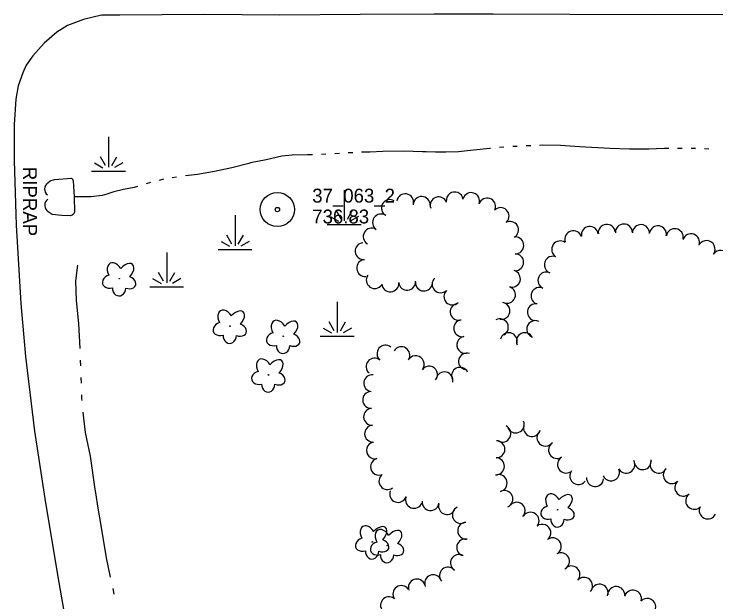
# Model space of a CAD drawing. Extents: x 589250 to 1188077, y 162953 to 363065.
# Drawn here: x 593139.8 to 593442.4, y 164801.7 to 165055.2 of the extents above; entities that cross this region are included whole.
import ezdxf

# ---------------------------------------------------------------- set-up
doc = ezdxf.new("R2010")
doc.units = 0
for name, color, linetype in [('E_DRN', 7, 'Continuous'), ('E_DRN_RipRap', 7, 'Continuous'), ('E_DRN_RipRap_Text', 7, 'Continuous'), ('E_LAND_TreeLine_P', 7, 'Continuous'), ('E_LAND_Vegetation', 7, 'Continuous'), ('E_MAP_PassPoints', 7, 'Continuous'), ('E_RDWY', 7, 'Continuous'), ('E_WTR_FlowLine', 7, 'Continuous'), ('E_WTR_Wetland', 7, 'Continuous')]:
    doc.layers.add(name, color=color, linetype=linetype)

# ---------------------------------------------------------------- blocks, each defined once
blk = doc.blocks.new('POINT_DISPLAY')
blk.add_line((0, 0), (0, 0))

msp = doc.modelspace()

# ---------------------------------------------------------------- linework, layer by layer
at = {"layer": 'E_DRN'}
for centre, radius, start, end in [((593156.19, 164979.78), 3.26, 125.1717, 231.4319), ((593156.45, 164972.77), 3.45, 128.3211, 234.5814)]:
    msp.add_arc(centre, radius, start, end, dxfattribs=at)
at = {"layer": 'E_DRN_RipRap'}
for p, q in [((593154.31, 164982.45), (593155.38, 164983.31)), ((593155.38, 164983.31), (593157.22, 164983.93)), ((593157.22, 164983.93), (593164.52, 164984.49)), ((593164.52, 164984.49), (593165.02, 164984.08)), ((593165.02, 164984.08), (593165.29, 164983.32)), ((593165.29, 164983.32), (593165.73, 164976.46)), ((593165.73, 164976.46), (593165.78, 164969.86)), ((593156.23, 164968.85), (593154.45, 164969.96)), ((593165.78, 164969.86), (593165.46, 164968.95)), ((593160.42, 164968.34), (593156.23, 164968.85)), ((593164.03, 164968.21), (593160.42, 164968.34)), ((593164.88, 164968.48), (593164.03, 164968.21)), ((593165.46, 164968.95), (593164.88, 164968.48))]:
    msp.add_line(p, q, dxfattribs=at)
at = {"layer": 'E_LAND_TreeLine_P'}
for centre, radius, start, end in [((593329.75, 164974.88), 3.64, 7.2134, 187.2134), ((593308.36, 164974.08), 3.64, 349.5475, 169.5475), ((593315.54, 164972.94), 3.64, 358.4967, 178.4967), ((593322.82, 164972.76), 3.64, 19.8862, 199.8862), ((593336.85, 164974.59), 3.64, 341.2448, 161.2448), ((593343.75, 164972.25), 3.64, 341.2448, 161.2448), ((593301.79, 164971.57), 3.64, 59.2686, 239.2686), ((593349.55, 164968.11), 3.64, 315.9963, 135.9963), ((593297.97, 164965.37), 3.64, 56.0727, 236.0727), ((593353.62, 164962.14), 3.64, 300.0679, 120.0679), ((593388.02, 164959.95), 3.68, 7.1667, 187.1667), ((593395.33, 164960.87), 3.68, 7.1667, 187.1667), ((593402.69, 164961.01), 3.68, 1.0281, 181.0281), ((593410.04, 164960.76), 3.68, 357.0874, 177.0874), ((593417.37, 164960.23), 3.68, 350.3061, 170.3061), ((593293.95, 164959.31), 3.64, 59.4309, 239.4309), ((593380.92, 164958.12), 3.68, 17.1599, 197.1599), ((593424.63, 164959), 3.68, 350.3061, 170.3061), ((593431.63, 164956.79), 3.68, 340.3602, 160.3602), ((593355.89, 164955.47), 3.64, 269.6417, 89.6417), ((593375.25, 164953.71), 3.68, 55.357, 235.357), ((593438.32, 164953.86), 3.68, 325.0659, 145.0659), ((593290.47, 164952.99), 3.64, 95.233, 275.233), ((593355.84, 164948.19), 3.64, 269.6417, 89.6417), ((593444.36, 164949.64), 3.68, 325.0659, 145.0659), ((593291.13, 164945.73), 3.64, 95.233, 275.233), ((593372.07, 164947.13), 3.68, 69.574, 249.574), ((593295.29, 164940.53), 3.64, 145.5372, 325.5372), ((593354.42, 164941.11), 3.64, 253.6584, 73.6584), ((593369.29, 164940.36), 3.64, 65.6946, 245.6946), ((593301.99, 164939.07), 3.64, 185.3245, 5.3245), ((593309.24, 164939.75), 3.64, 185.3245, 5.3245), ((593316.5, 164939.45), 3.64, 175.6585, 355.6585), ((593323.66, 164938.69), 3.64, 134.1091, 314.1091), ((593352.3, 164934.15), 3.64, 249.6763, 69.6763), ((593366.29, 164933.72), 3.64, 65.6946, 245.6946), ((593328.73, 164933.46), 3.64, 134.1091, 314.1091), ((593331.45, 164926.85), 3.64, 106.7367, 286.7367), ((593349.94, 164927.27), 3.64, 261.5592, 81.5592), ((593364.74, 164926.67), 3.64, 81.7612, 261.7612), ((593333.01, 164919.75), 3.64, 101.387, 281.387), ((593349.25, 164920.14), 3.64, 298.6014, 118.6014), ((593364.47, 164919.41), 3.64, 64.366, 244.366), ((593334.31, 164912.58), 3.64, 99.4623, 279.4623), ((593353.07, 164914.19), 3.64, 346.8399, 166.8399), ((593359.99, 164914.18), 3.64, 25.5786, 205.5786), ((593299.88, 164908.8), 3.64, 49.8325, 229.8325), ((593306.78, 164908.13), 3.64, 328.0612, 148.0612), ((593335.05, 164905.43), 3.64, 73.8428, 253.8428), ((593295.18, 164903.24), 3.64, 49.8325, 229.8325), ((593312.96, 164904.28), 3.64, 321.6912, 141.6912), ((593318.67, 164899.76), 3.64, 321.6912, 141.6912), ((593332.04, 164899.26), 3.64, 25.8734, 205.8734), ((593325.35, 164897.28), 3.64, 347.4748, 167.4748), ((593294.19, 164896.08), 3.64, 83.6957, 263.6957), ((593293.71, 164888.84), 3.64, 93.2452, 273.2452), ((593294.12, 164881.57), 3.64, 93.2452, 273.2452), ((593356.03, 164878.29), 3.68, 202.4814, 22.4814), ((593294.54, 164874.3), 3.64, 93.2452, 273.2452), ((593350.28, 164874.35), 3.68, 242.8248, 62.8248), ((593363.05, 164876.79), 3.68, 163.374, 343.374), ((593368.9, 164872.62), 3.68, 136.1872, 316.1872), ((593295.34, 164867.09), 3.64, 104.117, 284.117), ((593347.72, 164867.59), 3.68, 268.2345, 88.2345), ((593373.88, 164867.25), 3.68, 121.7546, 301.7546), ((593297.12, 164860.03), 3.64, 104.117, 284.117), ((593347.49, 164860.23), 3.68, 268.2345, 88.2345), ((593377.76, 164861), 3.68, 121.7546, 301.7546), ((593403.7, 164860.92), 3.68, 208.7555, 28.7555), ((593410.82, 164862.47), 3.68, 188.3625, 8.3625), ((593417.68, 164860.95), 3.68, 153.2365, 333.2365), ((593383.07, 164856.06), 3.68, 143.1155, 323.1155), ((593397.15, 164857.59), 3.68, 202.6582, 22.6582), ((593423.37, 164856.47), 3.68, 133.0012, 313.0012), ((593300.73, 164853.85), 3.64, 127.3492, 307.3492), ((593348.65, 164853), 3.68, 282.263, 102.263), ((593390.29, 164855.16), 3.68, 175.4687, 355.4687), ((593428.35, 164851.04), 3.68, 132.2967, 312.2967), ((593305.35, 164848.32), 3.64, 159.3779, 339.3779), ((593351.16, 164846.11), 3.68, 293.2579, 113.2579), ((593312.16, 164845.76), 3.64, 159.3779, 339.3779), ((593433.02, 164845.36), 3.68, 128.0263, 308.0263), ((593319.36, 164844.78), 3.64, 173.578, 353.578), ((593326.43, 164843.08), 3.64, 165.301, 345.301), ((593332.37, 164839.22), 3.64, 114.1949, 294.1949), ((593356.45, 164841.03), 3.68, 317.163, 137.163), ((593438.86, 164841.2), 3.68, 154.9547, 334.9547), ((593362.42, 164836.75), 3.68, 325.4363, 145.4363), ((593334.7, 164832.43), 3.64, 92.4781, 272.4781), ((593367.51, 164831.54), 3.68, 308.0551, 128.0551), ((593334.27, 164825.23), 3.64, 75.9097, 255.9097), ((593372.05, 164825.75), 3.68, 308.0551, 128.0551), ((593331.53, 164818.55), 3.64, 59.9759, 239.9759), ((593375.56, 164819.28), 3.68, 298.3049, 118.3049), ((593326.87, 164813.09), 3.64, 40.8337, 220.8337), ((593380.06, 164813.59), 3.68, 317.7585, 137.7585), ((593320.45, 164809.8), 3.64, 22.4814, 202.4814), ((593385.51, 164808.65), 3.68, 317.7585, 137.7585), ((593313.41, 164807.97), 3.64, 19.463, 199.463), ((593392.2, 164805.72), 3.68, 339.3779, 159.3779), ((593306.75, 164805.14), 3.64, 34.9275, 214.9275), ((593399.41, 164804.7), 3.68, 357.3215, 177.3215), ((593406.57, 164803.2), 3.68, 343.9383, 163.9383), ((593301.43, 164800.3), 3.64, 53.1593, 233.1593), ((593412.76, 164799.61), 3.68, 316.6645, 136.6645)]:
    msp.add_arc(centre, radius, start, end, dxfattribs=at)
at = {"layer": 'E_LAND_Vegetation'}
for centre in [(593185.13, 164941.12), (593232.83, 164920.67), (593255.84, 164916.3), (593249.45, 164899.62), (593374.14, 164841.48), (593294.2, 164827.67), (593300.66, 164826.05)]:
    msp.add_circle(centre, 0.128, dxfattribs=at)
for centre, major_axis, ratio in [((593183.2, 164944.08), (2.06, -3.68), 0.691916), ((593187.71, 164943.74), (-3.19, -3.52), 0.560249), ((593181.41, 164939.92), (3.48, 0.97), 0.782863), ((593188.8, 164939.52), (-3.4, 1.25), 0.716896), ((593185.03, 164937.14), (0.07, 3.45), 0.832022), ((593230.9, 164923.63), (2.06, -3.68), 0.691916), ((593235.41, 164923.29), (-3.19, -3.52), 0.560249), ((593229.11, 164919.47), (3.48, 0.97), 0.782863), ((593236.51, 164919.07), (-3.4, 1.25), 0.716896), ((593253.91, 164919.26), (2.06, -3.68), 0.691916), ((593258.42, 164918.92), (-3.19, -3.52), 0.560249), ((593232.74, 164916.69), (0.07, 3.45), 0.832022), ((593252.12, 164915.11), (3.48, 0.97), 0.782863), ((593259.51, 164914.7), (-3.4, 1.25), 0.716896), ((593255.75, 164912.32), (0.07, 3.45), 0.832022), ((593247.53, 164902.58), (2.06, -3.68), 0.691916), ((593252.04, 164902.24), (-3.19, -3.52), 0.560249), ((593245.73, 164898.43), (3.48, 0.97), 0.782863), ((593253.13, 164898.02), (-3.4, 1.25), 0.716896), ((593249.36, 164895.64), (0.07, 3.45), 0.832022), ((593372.21, 164844.44), (2.06, -3.68), 0.691916), ((593376.72, 164844.1), (-3.19, -3.52), 0.560249), ((593370.42, 164840.29), (3.48, 0.97), 0.782863), ((593377.81, 164839.88), (-3.4, 1.25), 0.716896), ((593374.05, 164837.5), (0.07, 3.45), 0.832022), ((593292.27, 164830.63), (2.06, -3.68), 0.691916), ((593296.78, 164830.29), (-3.19, -3.52), 0.560249), ((593298.73, 164829.01), (2.06, -3.68), 0.691916), ((593303.24, 164828.67), (-3.19, -3.52), 0.560249), ((593290.48, 164826.47), (3.48, 0.97), 0.782863), ((593296.94, 164824.86), (3.48, 0.97), 0.782863), ((593297.88, 164826.07), (-3.4, 1.25), 0.716896), ((593304.33, 164824.45), (-3.4, 1.25), 0.716896), ((593294.11, 164823.69), (0.07, 3.45), 0.832022), ((593300.57, 164822.07), (0.07, 3.45), 0.832022)]:
    msp.add_ellipse(centre, major_axis=major_axis, ratio=ratio, start_param=1.570796, end_param=4.712389, dxfattribs=at)
at = {"layer": 'E_MAP_PassPoints'}
for radius in [7.38, 0.945]:
    msp.add_circle((593253.31, 164970.94), radius, dxfattribs=at)
at = {"layer": 'E_RDWY'}
for p, q in [((593177.41, 165054.78), (593169.66, 165052.82)), ((593185.33, 165054.78), (593177.41, 165054.78)), ((593221.93, 165054.99), (593185.33, 165054.78)), ((593254.3, 165054.81), (593221.93, 165054.99)), ((593288.95, 165055.01), (593254.3, 165054.81)), ((593320.93, 165055.24), (593288.95, 165055.01)), ((593346.39, 165055.15), (593320.93, 165055.24)), ((593379.36, 165055.03), (593346.39, 165055.15)), ((593415.78, 165054.96), (593379.36, 165055.03)), ((593453.05, 165055.01), (593415.78, 165054.96)), ((593169.66, 165052.82), (593162.8, 165050.29)), ((593162.8, 165050.29), (593158.25, 165047.42)), ((593158.25, 165047.42), (593152.69, 165042.71)), ((593152.69, 165042.71), (593147.81, 165037.18)), ((593147.81, 165037.18), (593145.03, 165033.24)), ((593145.03, 165033.24), (593143.5, 165029.91)), ((593143.5, 165029.91), (593141.56, 165024.27)), ((593141.56, 165024.27), (593140.57, 165018.56)), ((593140.57, 165018.56), (593139.85, 165007.63)), ((593139.85, 165007.63), (593139.75, 164992.08)), ((593139.75, 164992.08), (593140.63, 164964.19)), ((593140.63, 164964.19), (593142.63, 164930.43)), ((593142.63, 164930.43), (593144.66, 164907.64)), ((593144.66, 164907.64), (593148.62, 164875.32)), ((593148.62, 164875.32), (593153.34, 164844.53)), ((593153.34, 164844.53), (593159.02, 164810.13)), ((593159.02, 164810.13), (593165.53, 164774.24))]:
    msp.add_line(p, q, dxfattribs=at)
at = {"layer": 'E_WTR_FlowLine'}
for p, q in [((593344.92, 164997.27), (593337.8, 164996.6)), ((593345.25, 164997.3), (593344.92, 164997.27)), ((593350.99, 164997.83), (593349.08, 164997.66)), ((593356.75, 164998.15), (593354.83, 164998.05)), ((593361.49, 164998.39), (593360.59, 164998.35)), ((593362.51, 164998.44), (593361.49, 164998.39)), ((593367.64, 164998.68), (593366.35, 164998.62)), ((593375.3, 164998.54), (593367.64, 164998.68)), ((593383.54, 164997.96), (593375.3, 164998.54)), ((593388.76, 164997.71), (593383.54, 164997.96)), ((593394.18, 164997.43), (593388.76, 164997.71)), ((593396.68, 164997.31), (593394.18, 164997.43)), ((593405.18, 164996.93), (593396.68, 164997.31)), ((593413.48, 164997.02), (593405.18, 164996.93)), ((593420.02, 164997.31), (593413.48, 164997.02)), ((593422.03, 164997.31), (593420.02, 164997.31)), ((593427.7, 164997.31), (593425.88, 164997.31)), ((593427.8, 164997.31), (593427.7, 164997.31)), ((593433.57, 164997.28), (593431.64, 164997.29)), ((593439.33, 164997.01), (593437.41, 164997.1)), ((593255.15, 164993.89), (593248.5, 164992.39)), ((593259.72, 164994.37), (593255.15, 164993.89)), ((593266.35, 164994.52), (593259.72, 164994.37)), ((593268.49, 164994.59), (593266.35, 164994.52)), ((593274.25, 164994.77), (593272.33, 164994.71)), ((593280.01, 164995.11), (593278.09, 164994.99)), ((593285.77, 164995.46), (593283.85, 164995.34)), ((593293.14, 164995.74), (593289.61, 164995.62)), ((593298.8, 164996.03), (593293.14, 164995.74)), ((593307.75, 164996.09), (593298.8, 164996.03)), ((593315.93, 164995.8), (593307.75, 164996.09)), ((593317.46, 164995.76), (593315.93, 164995.8)), ((593321.44, 164995.65), (593317.46, 164995.76)), ((593325.9, 164995.67), (593321.44, 164995.65)), ((593331.44, 164995.87), (593325.9, 164995.67)), ((593337.8, 164996.6), (593331.44, 164995.87)), ((593240.97, 164990.86), (593233.62, 164988.99)), ((593241.7, 164991.05), (593240.97, 164990.86)), ((593248.5, 164992.39), (593241.7, 164991.05)), ((593233.62, 164988.99), (593226.18, 164987.29)), ((593209.85, 164984.93), (593207.95, 164984.67)), ((593218.85, 164986.09), (593213.66, 164985.42)), ((593226.18, 164987.29), (593218.85, 164986.09)), ((593198.58, 164982.56), (593196.73, 164982.07)), ((593204.16, 164984.02), (593202.3, 164983.53)), ((593182.78, 164978.64), (593179.71, 164977.6)), ((593187, 164979.59), (593182.78, 164978.64)), ((593191.57, 164980.46), (593187, 164979.59)), ((593193.05, 164980.94), (593191.57, 164980.46)), ((593173.06, 164976.49), (593165.73, 164976.46)), ((593177.72, 164977.06), (593173.06, 164976.49)), ((593179.71, 164977.6), (593177.72, 164977.06)), ((593166.46, 164940.13), (593167.19, 164946.99)), ((593166.67, 164931.69), (593166.46, 164940.13)), ((593167.62, 164921.87), (593166.67, 164931.69)), ((593168.24, 164910.98), (593167.62, 164921.87)), ((593168.55, 164903.51), (593168.44, 164906)), ((593168.82, 164896.05), (593168.74, 164898.54)), ((593169.04, 164889.5), (593168.99, 164891.07)), ((593169.13, 164888.58), (593169.04, 164889.5)), ((593169.9, 164881), (593169.63, 164883.62)), ((593170.62, 164874.87), (593169.9, 164881)), ((593172.78, 164864.65), (593170.62, 164874.87)), ((593174.77, 164850.38), (593172.78, 164864.65)), ((593175.12, 164847.95), (593174.77, 164850.38)), ((593175.83, 164843.05), (593175.12, 164847.95)), ((593177.51, 164833.79), (593175.83, 164843.05)), ((593179.67, 164820.81), (593177.51, 164833.79)), ((593181.36, 164812.37), (593179.67, 164820.81)), ((593182.99, 164805.08), (593182.44, 164807.51))]:
    msp.add_line(p, q, dxfattribs=at)
at = {"layer": 'E_WTR_Wetland'}
for p, q in [((593180.52, 165002.36), (593180.52, 164989.16)), ((593179.17, 164989.91), (593177, 164993.7)), ((593181.93, 164989.91), (593184.09, 164993.7)), ((593174.46, 164991.05), (593178.09, 164988.99)), ((593186.64, 164991.05), (593183.01, 164989)), ((593173.22, 164987.53), (593187.78, 164987.54)), ((593282.12, 164979.26), (593282.13, 164966.06)), ((593280.77, 164966.81), (593278.6, 164970.6)), ((593283.53, 164966.82), (593285.7, 164970.61)), ((593235.04, 164968.53), (593235.05, 164955.32)), ((593276.06, 164967.95), (593279.69, 164965.9)), ((593288.24, 164967.96), (593284.62, 164965.9)), ((593274.82, 164964.43), (593289.38, 164964.44)), ((593233.7, 164956.08), (593231.53, 164959.87)), ((593236.46, 164956.08), (593238.62, 164959.87)), ((593228.99, 164957.22), (593232.61, 164955.16)), ((593241.17, 164957.22), (593237.54, 164955.16)), ((593205.57, 164952.48), (593205.58, 164939.28)), ((593227.74, 164953.7), (593242.3, 164953.7)), ((593204.22, 164940.03), (593202.06, 164943.82)), ((593206.99, 164940.04), (593209.15, 164943.83)), ((593199.52, 164941.17), (593203.14, 164939.12)), ((593211.7, 164941.18), (593208.07, 164939.12)), ((593198.27, 164937.65), (593212.83, 164937.66)), ((593279.1, 164931.15), (593279.11, 164917.94)), ((593277.75, 164918.7), (593275.59, 164922.49)), ((593280.51, 164918.7), (593282.68, 164922.49)), ((593273.05, 164919.83), (593276.67, 164917.78)), ((593285.22, 164919.84), (593281.6, 164917.78)), ((593271.8, 164916.32), (593286.36, 164916.32))]:
    msp.add_line(p, q, dxfattribs=at)

# ---------------------------------------------------------------- block references
at = {"layer": 'E_WTR_Wetland', "rotation": -0.02920029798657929}
for p in [(593180.52, 164990.42), (593180.52, 164989.16), (593180.06, 164987.53), (593180.54, 164987.53), (593180.61, 164987.53), (593282.12, 164967.32), (593281.66, 164964.43), (593282.13, 164966.06), (593282.15, 164964.43), (593282.21, 164964.43), (593235.05, 164956.58), (593235.05, 164955.32), (593234.58, 164953.7), (593235.07, 164953.7), (593235.13, 164953.7), (593205.58, 164940.54), (593205.58, 164939.28), (593205.11, 164937.65), (593205.6, 164937.65), (593205.66, 164937.65), (593279.11, 164919.2), (593279.11, 164917.94), (593278.64, 164916.32), (593279.13, 164916.32), (593279.19, 164916.32)]:
    msp.add_blockref('POINT_DISPLAY', p, dxfattribs=at)

# ---------------------------------------------------------------- texts
at = {"layer": 'E_DRN_RipRap_Text'}
msp.add_text('RIPRAP', height=6, rotation=270.2324, dxfattribs=at).set_placement((593143.57, 164989.33))
at = {"layer": 'E_MAP_PassPoints'}
for s, p in [('37_063_2', (593268.31, 164973.93)), ('736.83', (593268.31, 164964.93))]:
    msp.add_text(s, height=6, dxfattribs=at).set_placement(p)

doc.saveas('drawing.dxf')
